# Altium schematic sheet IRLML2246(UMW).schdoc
size 127 x 101 mm
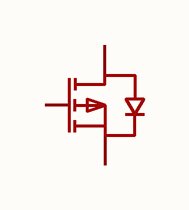
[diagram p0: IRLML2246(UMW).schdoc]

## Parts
Q?  irlml2246tr(umw)  [SOT-23-3_L2.9-W1.3-P1.90-LS2.4-BR]  (value not drawn)

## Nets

Not connected (* = marked no-connect by the designer): Q? 1(G) 2(S) 3(D)

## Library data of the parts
Q? = irlml2246tr(umw): 漏源电压(Vdss):20V;连续漏极电流(Id):2.6A;导通电阻(RDS(on)):90mΩ@4.5V；157mΩ@2.5V;耗散功率(Pd):1.3W;阈值电压(Vgs(th)):1.1V@10uA;; Manufacturer: UMW(友台半导体); Symbol: IRLML2246(UMW); AddInBom: yes; ModelId: c62791f0466c4ae2a892c056b845b0ca; ModelName: SOT-23-3P_L2.9-W1.3-H1.0-LS2.4-P0.95; ModelTransform: 98.425,114.173,0,180,0,0,0.0005,-0.0005,0; Drain to Source Voltage: 20V; Current - Continuous Drain(Id): 2.6A; Pd - Power Dissipation: 1.3W; Gate Charge(Qg): 2.9nC; Input Capacitance(Ciss): 220pF; Reverse Transfer Capacitance (Crss@Vds): 48pF; Output Capacitance(Coss): 70pF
